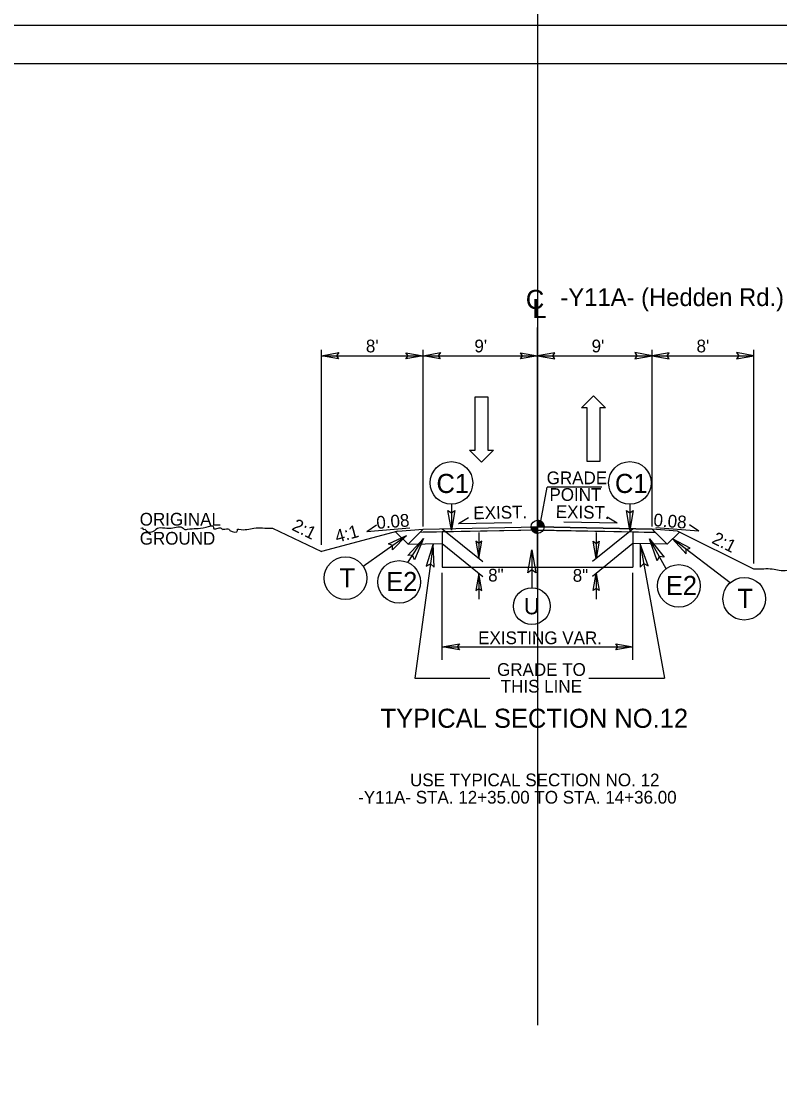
# Model space of a CAD drawing. Extents: x 18938 to 19565, y 6931 to 7973.
# Drawn here: x 19287.1 to 19346.7, y 7287.9 to 7371.6 of the extents above; entities that cross this region are included whole.
import ezdxf

# ---------------------------------------------------------------- set-up
doc = ezdxf.new("R2010")
doc.units = 0
for name, color, linetype in [('Old_Level_11', 7, 'Continuous'), ('Old_Level_2', 7, 'Continuous'), ('Old_Level_3', 7, 'Continuous'), ('Prop Dimension', 7, 'Continuous'), ('Prop Pavement Schedule Description CELL', 7, 'Continuous'), ('Prop Shade Medium', 7, 'Continuous'), ('Prop Terminator CELL', 7, 'Continuous'), ('Sheet Data Field CELL', 7, 'Continuous'), ('Sheet Plot Border Outside CELL', 7, 'Continuous'), ('Sheet Typical CELL', 7, 'Continuous'), ('Typical Curb CELL', 7, 'Continuous'), ('Typical Detail Wedge1 CELL', 7, 'Continuous'), ('Typical Detail Wedge2 CELL', 7, 'Continuous'), ('Typical Detail Wedge3 CELL', 7, 'Continuous'), ('Typical Guardrail CELL', 7, 'Continuous'), ('Typical Hinge Slope Arterial CELL', 7, 'Continuous'), ('Typical ID Circle CELL', 7, 'Continuous'), ('Typical Pavement Slope Information CELL', 7, 'Continuous'), ('Typical Shoulder Slope Information CELL', 7, 'Continuous'), ('Typical Terminator CELL', 7, 'Continuous'), ('Typical Text General CELL', 7, 'Continuous'), ('Typical Text Grade Point CELL', 7, 'Continuous'), ('Typical Text ID Circle CELL', 7, 'Continuous'), ('Typical Text Label CELL', 7, 'Continuous')]:
    doc.layers.add(name, color=color, linetype=linetype)

msp = doc.modelspace()

# ---------------------------------------------------------------- linework, layer by layer
at = {"layer": 'Old_Level_3'}
for p, q in [((19319.449, 7330.534), (19318.002, 7319.977)), ((19335.726, 7330.537), (19337.641, 7319.977)), ((19318.002, 7319.977), (19323.905, 7319.977)), ((19331.687, 7319.977), (19337.641, 7319.977))]:
    msp.add_line(p, q, dxfattribs=at)
at = {"layer": 'Prop Dimension'}
msp.add_lwpolyline([(19155.167, 7224.873), (19382.434, 7224.873), (19382.434, 7371.306), (19155.167, 7371.306)], close=True, dxfattribs=at)
at = {"layer": 'Prop Pavement Schedule Description CELL'}
for p, q in [((19317.469, 7330.52), (19316.485, 7331.503)), ((19316.659, 7331.55), (19318.659, 7331.71)), ((19317.469, 7330.52), (19318.659, 7331.71)), ((19318.404, 7331.455), (19318.659, 7331.71)), ((19320.158, 7331.49), (19318.404, 7331.455)), ((19318.659, 7331.71), (19327.658, 7331.89)), ((19336.658, 7331.71), (19327.658, 7331.89)), ((19335.158, 7331.49), (19336.913, 7331.455)), ((19337.849, 7330.52), (19336.658, 7331.71)), ((19338.658, 7331.55), (19336.658, 7331.71)), ((19337.849, 7330.52), (19338.806, 7331.476)), ((19344.658, 7328.55), (19338.658, 7331.55)), ((19317.469, 7330.52), (19320.158, 7330.573)), ((19337.849, 7330.52), (19335.158, 7330.573))]:
    msp.add_line(p, q, dxfattribs=at)
at = {"layer": 'Prop Shade Medium'}
for p in [(19306.805, 7331.782), (19316.659, 7331.55)]:
    msp.add_line(p, (19310.658, 7329.938), dxfattribs=at)
at = {"layer": 'Sheet Data Field CELL'}
for points in [[(19312.008, 7345.112), (19310.658, 7345.345), (19312.016, 7345.585), (19311.843, 7345.345)], [(19317.303, 7345.577), (19318.653, 7345.345), (19317.295, 7345.105), (19317.468, 7345.345)], [(19320.003, 7345.112), (19318.653, 7345.345), (19320.01, 7345.585), (19319.838, 7345.345)], [(19326.308, 7345.577), (19327.658, 7345.345), (19326.301, 7345.105), (19326.473, 7345.345)], [(19329.008, 7345.577), (19327.658, 7345.345), (19329.016, 7345.105), (19328.843, 7345.345)], [(19335.308, 7345.112), (19336.658, 7345.345), (19335.301, 7345.585), (19335.473, 7345.345)], [(19338.008, 7345.577), (19336.658, 7345.345), (19338.016, 7345.105), (19337.843, 7345.345)], [(19343.308, 7345.112), (19344.658, 7345.345), (19343.301, 7345.585), (19343.473, 7345.345)], [(19317.451, 7329.638), (19318.688, 7330.982), (19317.975, 7329.288), (19317.831, 7329.654)], [(19319.512, 7328.722), (19319.449, 7330.547), (19318.886, 7328.797), (19319.235, 7328.982)], [(19322.811, 7330.753), (19323.043, 7329.403), (19323.283, 7330.761), (19323.043, 7330.588)], [(19332.506, 7330.753), (19332.273, 7329.403), (19332.033, 7330.761), (19332.273, 7330.588)], [(19336.348, 7328.834), (19335.722, 7330.549), (19335.73, 7328.711), (19336.004, 7328.995)], [(19337.055, 7329.209), (19336.454, 7330.934), (19337.611, 7329.506), (19337.22, 7329.552)], [(19326.897, 7328.283), (19327.207, 7330.083), (19327.527, 7328.273), (19327.207, 7328.503)], [(19323.278, 7326.88), (19323.046, 7328.23), (19322.806, 7326.872), (19323.046, 7327.045)], [(19332.038, 7326.88), (19332.27, 7328.23), (19332.51, 7326.872), (19332.27, 7327.045)], [(19321.508, 7322.218), (19320.158, 7322.45), (19321.516, 7322.69), (19321.343, 7322.45)], [(19333.808, 7322.683), (19335.158, 7322.45), (19333.801, 7322.21), (19333.973, 7322.45)]]:
    msp.add_lwpolyline(points, close=True, dxfattribs=at)
at = {"layer": 'Sheet Typical CELL'}
for p, q in [((19310.658, 7330.472), (19310.658, 7345.805)), ((19310.658, 7345.345), (19344.658, 7345.345)), ((19318.653, 7345.345), (19327.658, 7345.345)), ((19318.658, 7331.91), (19318.658, 7345.805)), ((19336.658, 7331.929), (19336.658, 7345.805)), ((19344.658, 7329.01), (19344.658, 7345.805)), ((19320.155, 7331.743), (19323.342, 7329.161)), ((19323.043, 7331.447), (19323.043, 7329.403)), ((19335.162, 7331.743), (19331.974, 7329.161)), ((19332.273, 7331.447), (19332.273, 7329.403)), ((19320.158, 7330.573), (19323.346, 7327.992)), ((19335.158, 7330.573), (19331.971, 7327.992)), ((19320.158, 7321.421), (19320.158, 7328.265)), ((19323.046, 7328.23), (19323.046, 7326.206)), ((19332.27, 7328.23), (19332.27, 7326.206)), ((19335.158, 7321.421), (19335.158, 7328.265)), ((19320.158, 7322.45), (19335.158, 7322.45))]:
    msp.add_line(p, q, dxfattribs=at)
at = {"layer": 'Typical Curb CELL'}
for points in [[(19296.44, 7331.782), (19296.612, 7331.782), (19296.612, 7331.696), (19296.783, 7331.696), (19296.869, 7331.61), (19297.554, 7331.61), (19297.639, 7331.696), (19298.839, 7331.782), (19299.781, 7331.782), (19299.866, 7331.696), (19300.124, 7331.696), (19301.58, 7331.867), (19302.179, 7331.867), (19302.179, 7331.782), (19302.779, 7331.782), (19302.864, 7331.696), (19302.95, 7331.696), (19303.378, 7331.696), (19303.464, 7331.61), (19304.063, 7331.61), (19304.063, 7331.696), (19304.149, 7331.696), (19305.348, 7331.782), (19306.719, 7331.782), (19306.805, 7331.782)], [(19355.023, 7328.55), (19354.851, 7328.55), (19354.851, 7328.464), (19354.68, 7328.464), (19354.594, 7328.379), (19353.909, 7328.379), (19353.823, 7328.464), (19352.624, 7328.55), (19351.682, 7328.55), (19351.596, 7328.464), (19351.339, 7328.464), (19349.883, 7328.636), (19349.284, 7328.636), (19349.284, 7328.55), (19348.684, 7328.55), (19348.598, 7328.464), (19348.513, 7328.464), (19348.084, 7328.464), (19347.999, 7328.379), (19347.399, 7328.379), (19347.399, 7328.464), (19347.314, 7328.464), (19346.115, 7328.55), (19344.744, 7328.55), (19344.658, 7328.55)]]:
    msp.add_spline(points, degree=3, dxfattribs=at)
at = {"layer": 'Typical Detail Wedge1 CELL'}
for p, q in [((19327.658, 7331.89), (19327.658, 7332.402)), ((19327.146, 7331.89), (19327.658, 7331.89)), ((19328.17, 7331.89), (19327.658, 7331.89)), ((19327.658, 7331.378), (19327.658, 7331.89)), ((19327.658, 7331.89), (19327.658, 7331.378))]:
    msp.add_line(p, q, dxfattribs=at)
for points in [[(19327.663, 7332.402), (19327.663, 7332.402), (19327.663, 7331.89)], [(19327.674, 7332.402), (19327.673, 7331.89)], [(19327.684, 7332.401), (19327.684, 7331.89)], [(19327.694, 7332.401), (19327.694, 7331.89)], [(19327.704, 7332.4), (19327.704, 7331.89)], [(19327.714, 7332.399), (19327.714, 7331.89)], [(19327.725, 7332.398), (19327.725, 7331.89)], [(19327.735, 7332.396), (19327.735, 7331.89)], [(19327.745, 7332.394), (19327.745, 7331.89)], [(19327.755, 7332.393), (19327.755, 7331.89)], [(19327.766, 7332.391), (19327.765, 7331.89)], [(19327.776, 7332.388), (19327.776, 7331.89)], [(19327.786, 7332.386), (19327.786, 7331.89)], [(19327.796, 7332.383), (19327.796, 7331.89)], [(19327.807, 7332.38), (19327.807, 7331.89)], [(19327.817, 7332.377), (19327.817, 7331.89)], [(19327.827, 7332.374), (19327.827, 7331.89)], [(19327.838, 7332.369), (19327.837, 7331.89)], [(19327.848, 7332.366), (19327.848, 7331.89)], [(19327.858, 7332.362), (19327.858, 7331.89)], [(19327.868, 7332.357), (19327.868, 7331.89)], [(19327.878, 7332.352), (19327.878, 7331.89)], [(19327.889, 7332.347), (19327.889, 7331.89)], [(19327.899, 7332.342), (19327.899, 7331.89)], [(19327.909, 7332.336), (19327.909, 7331.89)], [(19327.919, 7332.33), (19327.919, 7331.89)], [(19327.93, 7332.324), (19327.929, 7331.89)], [(19327.94, 7332.318), (19327.94, 7331.89)], [(19327.95, 7332.311), (19327.95, 7331.89)], [(19327.96, 7332.303), (19327.96, 7331.89)], [(19327.97, 7332.296), (19327.97, 7331.89)], [(19327.981, 7332.288), (19327.98, 7331.89)], [(19327.991, 7332.279), (19327.991, 7331.89)], [(19328.001, 7332.27), (19328.001, 7331.89)], [(19328.011, 7332.26), (19328.011, 7331.89)], [(19328.022, 7332.25), (19328.022, 7331.89)], [(19328.032, 7332.24), (19328.032, 7331.89)], [(19328.042, 7332.229), (19328.042, 7331.89)], [(19328.053, 7332.216), (19328.052, 7331.89)], [(19328.063, 7332.204), (19328.063, 7331.89)], [(19328.073, 7332.19), (19328.073, 7331.89)], [(19328.083, 7332.176), (19328.083, 7331.89)], [(19328.093, 7332.16), (19328.093, 7331.89)], [(19328.104, 7332.142), (19328.104, 7331.89)], [(19328.114, 7332.124), (19328.114, 7331.89)], [(19328.124, 7332.102), (19328.124, 7331.89)], [(19328.134, 7332.078), (19328.134, 7331.89)], [(19328.144, 7332.05), (19328.144, 7331.89)], [(19328.155, 7332.014), (19328.155, 7331.89)], [(19328.165, 7331.963), (19328.165, 7331.89)], [(19327.149, 7331.89), (19327.149, 7331.834)], [(19327.16, 7331.89), (19327.16, 7331.774)], [(19327.17, 7331.89), (19327.17, 7331.737)], [(19327.18, 7331.89), (19327.18, 7331.707)], [(19327.19, 7331.89), (19327.19, 7331.682)], [(19327.2, 7331.89), (19327.2, 7331.661)], [(19327.211, 7331.89), (19327.211, 7331.641)], [(19327.221, 7331.89), (19327.221, 7331.624)], [(19327.231, 7331.89), (19327.231, 7331.608)], [(19327.241, 7331.89), (19327.241, 7331.593)], [(19327.252, 7331.89), (19327.252, 7331.579)], [(19327.262, 7331.89), (19327.262, 7331.566)], [(19327.272, 7331.89), (19327.272, 7331.554)], [(19327.282, 7331.89), (19327.282, 7331.542)], [(19327.292, 7331.89), (19327.292, 7331.532)], [(19327.303, 7331.89), (19327.303, 7331.522)], [(19327.313, 7331.89), (19327.313, 7331.512)], [(19327.323, 7331.89), (19327.323, 7331.503)], [(19327.334, 7331.89), (19327.334, 7331.494)], [(19327.344, 7331.89), (19327.344, 7331.486)], [(19327.354, 7331.89), (19327.354, 7331.478)], [(19327.364, 7331.89), (19327.364, 7331.471)], [(19327.375, 7331.89), (19327.374, 7331.464)], [(19327.385, 7331.89), (19327.385, 7331.457)], [(19327.395, 7331.89), (19327.395, 7331.451)], [(19327.405, 7331.89), (19327.405, 7331.445)], [(19327.415, 7331.89), (19327.415, 7331.439)], [(19327.426, 7331.89), (19327.426, 7331.434)], [(19327.436, 7331.89), (19327.436, 7331.429)], [(19327.446, 7331.89), (19327.446, 7331.424)], [(19327.456, 7331.89), (19327.456, 7331.419)], [(19327.467, 7331.89), (19327.466, 7331.415)], [(19327.477, 7331.89), (19327.477, 7331.411)], [(19327.487, 7331.89), (19327.487, 7331.407)], [(19327.497, 7331.89), (19327.497, 7331.404)], [(19327.507, 7331.89), (19327.507, 7331.401)], [(19327.518, 7331.89), (19327.518, 7331.398)], [(19327.528, 7331.89), (19327.528, 7331.395)], [(19327.538, 7331.89), (19327.538, 7331.392)], [(19327.549, 7331.89), (19327.549, 7331.39)], [(19327.559, 7331.89), (19327.559, 7331.388)], [(19327.569, 7331.89), (19327.569, 7331.386)], [(19327.579, 7331.89), (19327.579, 7331.384)], [(19327.59, 7331.89), (19327.59, 7331.382)], [(19327.6, 7331.89), (19327.6, 7331.381)], [(19327.61, 7331.89), (19327.61, 7331.38)], [(19327.62, 7331.89), (19327.62, 7331.379)], [(19327.631, 7331.89), (19327.63, 7331.379)], [(19327.641, 7331.89), (19327.641, 7331.378)], [(19327.651, 7331.89), (19327.651, 7331.378), (19327.651, 7331.378)]]:
    msp.add_lwpolyline(points, dxfattribs=at)
msp.add_circle((19327.658, 7331.89), 0.512, dxfattribs=at)
for start, end in [(359.99048, 89.99048), (179.99048, 269.99048)]:
    msp.add_arc((19327.658, 7331.89), 0.512, start, end, dxfattribs=at)
at = {"layer": 'Typical Detail Wedge3 CELL'}
for p, q in [((19322.744, 7337.908), (19322.744, 7342.108)), ((19322.744, 7342.108), (19323.734, 7342.108)), ((19323.734, 7342.108), (19323.734, 7337.908)), ((19331.113, 7341.237), (19332.043, 7342.182)), ((19332.043, 7342.182), (19333.003, 7341.237)), ((19331.563, 7341.237), (19331.113, 7341.237)), ((19331.563, 7337.037), (19331.563, 7341.237)), ((19333.003, 7341.237), (19332.553, 7341.237)), ((19332.553, 7341.237), (19332.553, 7337.037)), ((19323.254, 7336.963), (19322.294, 7337.908)), ((19322.294, 7337.908), (19322.744, 7337.908)), ((19324.184, 7337.908), (19323.254, 7336.963)), ((19323.734, 7337.908), (19324.184, 7337.908)), ((19332.553, 7337.037), (19331.563, 7337.037))]:
    msp.add_line(p, q, dxfattribs=at)
at = {"layer": 'Typical Guardrail CELL'}
msp.add_line((19327.658, 7635.751), (19327.658, 7292.693), dxfattribs=at)
at = {"layer": 'Typical Hinge Slope Arterial CELL'}
for p, q in [((19318.403, 7331.455), (19318.659, 7331.71)), ((19327.658, 7331.64), (19318.403, 7331.455)), ((19318.403, 7331.455), (19318.403, 7331.455)), ((19318.403, 7331.455), (19318.403, 7331.455)), ((19318.659, 7331.71), (19327.658, 7331.89)), ((19327.658, 7331.89), (19336.658, 7331.71)), ((19336.913, 7331.455), (19327.658, 7331.64)), ((19336.658, 7331.71), (19336.913, 7331.455))]:
    msp.add_line(p, q, dxfattribs=at)
at = {"layer": 'Typical ID Circle CELL'}
for p, q in [((19327.658, 7331.64), (19318.659, 7331.46)), ((19320.158, 7331.49), (19320.158, 7328.709)), ((19327.658, 7331.64), (19336.658, 7331.46)), ((19335.158, 7331.49), (19335.158, 7328.709)), ((19320.158, 7328.709), (19335.158, 7328.709))]:
    msp.add_line(p, q, dxfattribs=at)
at = {"layer": 'Typical Pavement Slope Information CELL'}
msp.add_lwpolyline([(19380.142, 7368.299), (19177.642, 7368.299), (19177.642, 7227.884), (19380.142, 7227.884)], close=True, dxfattribs=at)
at = {"layer": 'Typical Terminator CELL'}
for p, q in [((19320.875, 7333.664), (19320.875, 7331.623)), ((19334.917, 7333.664), (19334.917, 7331.623)), ((19313.929, 7328.804), (19317.35, 7331.215)), ((19317.46, 7329.08), (19318.688, 7330.982)), ((19337.757, 7328.583), (19336.454, 7330.934)), ((19342.79, 7327.481), (19338.263, 7330.934)), ((19327.207, 7330.083), (19327.207, 7327.1))]:
    msp.add_line(p, q, dxfattribs=at)
for centre, radius in [((19320.875, 7335.34), 1.676), ((19334.917, 7335.34), 1.676), ((19312.547, 7327.856), 1.676), ((19316.767, 7327.554), 1.676), ((19338.765, 7327.245), 1.676), ((19343.913, 7326.237), 1.676), ((19327.207, 7325.657), 1.443)]:
    msp.add_circle(centre, radius, dxfattribs=at)
at = {"layer": 'Typical Text General CELL'}
for points in [[(19321.143, 7333.175), (19320.875, 7331.623), (19320.599, 7333.183), (19320.875, 7332.985)], [(19335.184, 7333.175), (19334.917, 7331.623), (19334.641, 7333.183), (19334.917, 7332.985)], [(19315.928, 7330.54), (19317.35, 7331.215), (19316.233, 7330.091), (19316.237, 7330.431)], [(19339.659, 7330.205), (19338.263, 7330.934), (19339.336, 7329.768), (19339.346, 7330.107)]]:
    msp.add_lwpolyline(points, close=True, dxfattribs=at)
at = {"layer": 'Typical Text Grade Point CELL'}
for p, q in [((19314.227, 7331.531), (19314.98, 7332.05)), ((19321.443, 7332.146), (19322.226, 7332.619)), ((19321.443, 7332.146), (19325.632, 7332.23)), ((19333.902, 7332.184), (19329.713, 7332.267)), ((19333.902, 7332.184), (19333.119, 7332.657)), ((19340.345, 7331.538), (19339.592, 7332.058)), ((19314.227, 7331.531), (19317.613, 7331.802)), ((19340.345, 7331.538), (19336.959, 7331.809))]:
    msp.add_line(p, q, dxfattribs=at)
at = {"layer": 'Typical Text ID Circle CELL'}
for p, q in [((19327.658, 7327.094), (19327.658, 7347.567)), ((19327.908, 7332.343), (19328.404, 7335.011)), ((19332.719, 7335.011), (19328.404, 7335.011))]:
    msp.add_line(p, q, dxfattribs=at)

# ---------------------------------------------------------------- texts
at = {"layer": 'Old_Level_11'}
for s, height, p in [('GRADE TO', 1, (19324.466, 7320.169)), ('THIS LINE', 1, (19324.757, 7318.858)), ('TYPICAL SECTION NO.12', 1.5, (19315.304, 7316.087)), ('USE TYPICAL SECTION NO. 12', 1, (19317.624, 7311.487))]:
    msp.add_text(s, height=height, dxfattribs=at).set_placement(p)
at = {"layer": 'Old_Level_2'}
for s, p in [('ORIGINAL', (19296.364, 7331.988)), ('GROUND', (19296.364, 7330.488))]:
    msp.add_text(s, height=1, rotation=360, dxfattribs=at).set_placement(p)
at = {"layer": 'Prop Terminator CELL'}
for s, height, p in [('C1', 1.5, (19319.702, 7334.552)), ('C1', 1.5, (19333.743, 7334.552)), ('E2', 1.5, (19315.744, 7326.842)), ('E2', 1.5, (19337.742, 7326.533)), ('T', 1.5, (19343.369, 7325.517)), ('U', 1.291, (19326.575, 7325.012))]:
    msp.add_text(s, height=height, dxfattribs=at).set_placement(p)
msp.add_text('T', height=1.5, rotation=360, dxfattribs=at).set_placement((19312.078, 7327.136))
at = {"layer": 'Sheet Plot Border Outside CELL'}
for s, p in [('GRADE', (19328.37, 7335.241)), ('POINT', (19328.588, 7333.931))]:
    msp.add_text(s, height=1, rotation=0.00004, dxfattribs=at).set_placement(p)
at = {"layer": 'Typical Detail Wedge2 CELL'}
for s, p in [("8'", (19314.15, 7345.609)), ("9'", (19322.687, 7345.609)), ("9'", (19331.905, 7345.609)), ("8'", (19340.155, 7345.609)), ('8"', (19323.768, 7327.591)), ('8"', (19330.42, 7327.572)), ('EXISTING VAR.', (19322.983, 7322.662)), ('-Y11A- STA. 12+35.00 TO STA. 14+36.00', (19313.542, 7310.126))]:
    msp.add_text(s, height=1, dxfattribs=at).set_placement(p)
at = {"layer": 'Typical Shoulder Slope Information CELL'}
for s, rotation, p in [('2:1', 333.43491, (19308.262, 7331.683)), ('4:1', 15.1346, (19311.875, 7330.626)), ('2:1', 333.43491, (19341.288, 7330.649))]:
    msp.add_text(s, height=1, rotation=rotation, dxfattribs=at).set_placement(p)
at = {"layer": 'Typical Text Grade Point CELL'}
for s, rotation, p in [('0.08', 4.5738, (19315.015, 7331.719)), ('EXIST.', 1.14574, (19322.611, 7332.481)), ('EXIST.', 358.85426, (19329.078, 7332.591)), ('0.08', 355.4262, (19336.741, 7331.952))]:
    msp.add_text(s, height=1, rotation=rotation, dxfattribs=at).set_placement(p)
at = {"layer": 'Typical Text Label CELL'}
for s, height, p in [('C', 1.5, (19326.729, 7349.021)), ('-Y11A- (Hedden Rd.)', 1.4, (19329.45, 7349.25)), ('L', 1.5, (19327.246, 7348.314))]:
    msp.add_text(s, height=height, dxfattribs=at).set_placement(p)

doc.saveas('drawing.dxf')
